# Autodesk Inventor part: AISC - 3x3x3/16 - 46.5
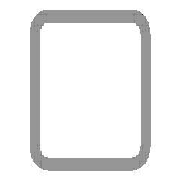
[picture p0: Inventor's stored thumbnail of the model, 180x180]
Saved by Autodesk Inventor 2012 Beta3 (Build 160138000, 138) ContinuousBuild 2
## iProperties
_CCFamilyMember: 9
_CCFamilyDisplayName: ANSI AISC (Square) - Tube
_FrameMemberDoc: Frame Member File
_Version: 15.0.0
_GetPNFromCC: 1
Created: 2011-01
Part Number: AISC - 3x3x3/16 - 46.5
Material: Steel, Mild
Description: Tube
Document SubType Name: Modeling
Standard: ANSI
Designer: Beta-8540w
Standards Organization: ANSI
Language: en-US
Size Designation: 3x3x3/16
Categories: <MemberInstance><Categories><Category DisplayName="Structural Shapes" InternalName="089c4875-fa83-4c05-b084-43b9cc11f5ed" Mnemonic="GRDR"><CategoryParameter Dis
Stock Number: 3x3x3/16
Density: 7.86 g/cm^3
IsCustomPart: 1
G_L: 46.500 in
G_W: 3.000 in
G_H: 3.000 in
Author: Beta-8540w
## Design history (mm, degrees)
node "Start plane"
node "End plane"
sketch "Sketch"
  geometry: L1 (-38.1, -28.575)-(-38.1, 28.575); L2 (-28.575, 38.1)-(28.575, 38.1); L3 (38.1, 28.575)-(38.1, -28.575); L4 (28.575, -38.1)-(-28.575, -38.1); L5 (-28.575, 33.337)-(28.575, 33.338); L6 (33.338, 28.575)-(33.338, -28.575); L7 (28.575, -33.337)-(-28.575, -33.338); L8 (-33.338, -28.575)-(-33.338, 28.575); L9 (0, 56.102)-(0, -56.102) reference; L10 (-56.102, 0)-(56.102, 0) reference; A1 r 9.525 centre (-28.575, -28.575) between (-38.1, -28.575) and (-28.575, -38.1); A2 r 9.525 centre (-28.575, 28.575) between (-28.575, 38.1) and (-38.1, 28.575); A3 r 9.525 centre (28.575, 28.575) between (38.1, 28.575) and (28.575, 38.1); A4 r 9.525 centre (28.575, -28.575) between (28.575, -38.1) and (38.1, -28.575); A5 r 4.763 centre (-28.575, 28.575) between (-28.575, 33.337) and (-33.338, 28.575); A6 r 4.763 centre (28.575, 28.575) between (33.338, 28.575) and (28.575, 33.338); A7 r 4.763 centre (28.575, -28.575) between (28.575, -33.337) and (33.338, -28.575); A8 r 4.763 centre (-28.575, -28.575) between (-33.338, -28.575) and (-28.575, -33.338)
  constraints: 16 end point, 16 point on circle, 8 centre point, 8 tangent, 4 parallel, 3 equal radius, 2 perpendicular, 7 other
  dimensions: "d10" = 76.2 distance between parallel lines of L2 L4 (= G_H); "d11" = 76.2 distance between parallel lines of L1 L3 (= G_W); "d12" = 4.7625 distance between parallel lines of L3 L6 (= G_T); "d15" = 38.1 distance between parallel lines of L2 L10 (= 0.5 x d10); "d16" = 38.1 distance between parallel lines of L9 L3 (= 0.5 x d11); "d17" = 9.525 radius of A1 (= G_IR)
extrude "Body" new body sketch "Sketch" stored distance "d3" = 1181.1 (= G_L); taper "d4" = 0 deg
node "Driven Length"
  sketch "Sketch3"
    geometry: L1 (0, 0)-(10, 0) reference
    constraints: 2 end point, 1 horizontal
  workplane "Work Plane3"
  sketch "Sketch4"
    geometry: L1 (-2, 38.1)-(12, 38.1) reference; L2 (-2, 1219.2)-(12, 1219.2) reference
    dimensions: "d19" = 1181.1 distance between parallel lines of L1 L2 (derived)
workplane "Work Plane4"
split "Split1"
body "Solid1"
other parameters: "G_W" = 76.2 [user parameter; used in 1 equation term], "G_H" = 76.2 [user parameter; used in 1 equation term], "G_T" = 4.7625 [user parameter; used in 1 equation term], "G_IR" = 9.525 [user parameter; used in 1 equation term], "G_L" = 1181.1 (= d19) [user parameter; used in 1 equation term], "G_OFFSET_START" = -38.1 [user parameter; used in 1 equation term], "G_OFFSET_END" = 0 [user parameter; used in 1 equation term], "d13" = 38.1 (= -G_OFFSET_START), "d14" = 1219.2 (= G_OFFSET_END + B_L), "B_L" = 1219.2 [user parameter; used in 1 equation term], "d18" = 90 deg
